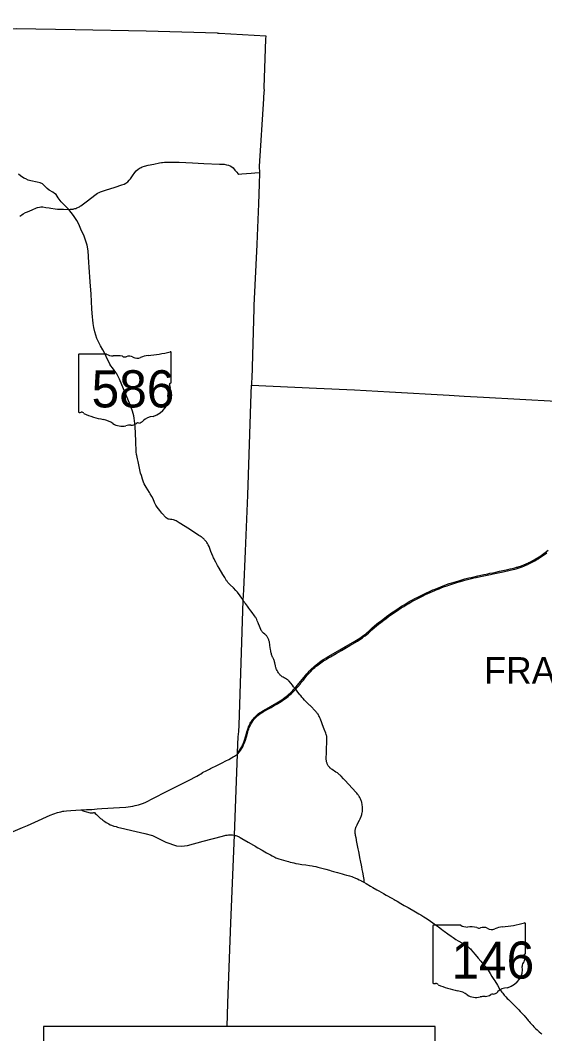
# Model space of a CAD drawing. Extents: x 1761803 to 2441803, y 509895 to 949895.
# Drawn here: x 2038611 to 2077957, y 835674 to 911653 of the extents above; entities that cross this region are included whole.
import ezdxf

# ---------------------------------------------------------------- set-up
doc = ezdxf.new("R2010")
doc.units = 0
for name, color, linetype in [('GM_X_County', 7, 'Continuous'), ('GM_X_County_Road', 7, 'Continuous'), ('GM_X_Minor_Lake', 7, 'Continuous'), ('GM_X_State_Location', 7, 'Continuous'), ('GM_X_Township_Road', 7, 'Continuous')]:
    doc.layers.add(name, color=color, linetype=linetype)

msp = doc.modelspace()

# ---------------------------------------------------------------- linework, layer by layer
at = {"layer": 'GM_X_County'}
for points in [[(2053400, 910687), (2048066, 910835), (2042725, 910935), (2038298, 911006), (2034985, 910966), (2034493, 910970), (2032253, 910990), (2029643, 910984), (2029631, 910665), (2029362, 910671), (2028709, 910661), (2023356, 910714), (2021728, 910742), (2020383, 910765), (2017999, 910806), (2014117, 910901), (2012614, 910938), (2008904, 911114), (2007002, 911215), (2006296, 911251), (2001880, 911522), (2001221, 911534), (2000194, 911593), (1998869, 911653)], [(2053400, 910687), (2053533, 910684), (2057032, 910483), (2057020, 910247), (2056883, 906617), (2056881, 906520), (2056896, 906456), (2056847, 905908), (2056862, 905765), (2056542, 900719), (2056569, 900221), (2056539, 899360), (2056483, 897899), (2056382, 895495), (2056352, 894837), (2056131, 890278), (2056126, 890080), (2056132, 890032), (2056081, 888304), (2055974, 884769), (2055968, 884562), (2055950, 884428), (2055947, 884303), (2060827, 884062), (2063674, 883938), (2066322, 883788), (2070793, 883546), (2071923, 883478), (2073355, 883403), (2078806, 883101)], [(2054132, 836223), (2054183, 837975), (2054401, 843988), (2054673, 850556), (2054916, 856641), (2054919, 856750), (2054960, 857935), (2055001, 858323), (2055024, 858817), (2055344, 868144), (2055389, 868960), (2055514, 871840), (2055675, 876040), (2055921, 883683), (2055947, 884303)]]:
    msp.add_lwpolyline(points, dxfattribs=at)
at = {"layer": 'GM_X_Minor_Lake'}
for points in [[(2043159, 897748), (2043164, 897752), (2043454, 897969), (2043549, 898040), (2044314, 898625), (2044412, 898680), (2044524, 898742), (2044623, 898784), (2045008, 898904), (2045734, 899132), (2046225, 899304), (2046407, 899368), (2046537, 899434), (2046617, 899484), (2046683, 899550), (2046787, 899663), (2046872, 899772), (2047037, 899982), (2047202, 900232), (2047300, 900357), (2047452, 900484), (2047618, 900593), (2047688, 900621), (2047759, 900655), (2047929, 900709), (2048217, 900781), (2048630, 900859), (2049051, 900960), (2049195, 900984), (2049290, 900996), (2049438, 901010), (2049872, 901014), (2050540, 901010), (2051529, 900968), (2052383, 900923), (2053556, 900872), (2053908, 900854), (2054094, 900823), (2054228, 900785), (2054346, 900741), (2054479, 900665), (2054579, 900585), (2054719, 900425), (2054857, 900253), (2054942, 900160), (2054996, 900120), (2055223, 900130), (2055592, 900161), (2055927, 900188), (2056211, 900220), (2056568, 900235)], [(2047305, 879302), (2047294, 879563), (2047287, 879832), (2047286, 880010), (2047267, 880785), (2047198, 881451), (2047128, 881989), (2047036, 882341), (2046852, 882829), (2046067, 884739), (2045962, 884941), (2045911, 885035), (2045852, 885135), (2045772, 885255), (2045534, 885586), (2045403, 885755), (2045335, 885870), (2045246, 886045), (2045088, 886370), (2045024, 886509), (2044809, 886947), (2044629, 887250), (2044344, 887785), (2044203, 888304), (2044137, 888614), (2044092, 888908), (2044057, 889188), (2044031, 889403), (2043985, 890011), (2043927, 891116), (2043856, 892033), (2043783, 893155), (2043764, 893487), (2043700, 894371), (2043637, 894784), (2043413, 895466), (2043167, 896000), (2042996, 896365), (2042862, 896635), (2042599, 897028), (2042258, 897474), (2042021, 897691), (2041816, 897905), (2041692, 898051), (2041456, 898345), (2041293, 898579), (2041189, 898673), (2041048, 898761), (2040783, 898909), (2040632, 899030), (2040354, 899308), (2040267, 899394), (2040116, 899455), (2039873, 899513), (2039404, 899623), (2039204, 899675), (2039026, 899758), (2038880, 899823), (2038621, 899990), (2038489, 900117)], [(2038580, 896972), (2038719, 897066), (2038840, 897145), (2038998, 897233), (2039156, 897299), (2039325, 897375), (2039499, 897451), (2039827, 897593), (2039903, 897613), (2040054, 897640), (2040149, 897657), (2040219, 897662), (2040300, 897660), (2040521, 897627), (2040770, 897580), (2040903, 897562), (2041226, 897512), (2041406, 897495), (2041590, 897486), (2041863, 897489), (2042258, 897474), (2042359, 897480), (2042419, 897485), (2042537, 897493), (2042583, 897500), (2042635, 897511), (2042707, 897530), (2042771, 897552), (2042866, 897586), (2042968, 897631), (2043053, 897675), (2043115, 897716), (2043159, 897748)], [(2055344, 868144), (2055242, 868319), (2055100, 868508), (2054914, 868768), (2054781, 868913), (2054606, 869097), (2054367, 869333), (2054307, 869390), (2054191, 869512), (2054125, 869598), (2054095, 869638), (2053957, 869865), (2053814, 870097), (2053531, 870579), (2053418, 870780), (2053279, 871019), (2053181, 871198), (2053146, 871266), (2053106, 871350), (2053072, 871417), (2053051, 871469), (2052980, 871647), (2052908, 871823), (2052880, 871898), (2052774, 872194), (2052713, 872327), (2052654, 872429), (2052612, 872495), (2052577, 872546), (2052528, 872610), (2052486, 872659), (2052443, 872707), (2052404, 872745), (2052352, 872794), (2052315, 872824), (2052278, 872855), (2052221, 872896), (2052179, 872924), (2052116, 872965), (2052059, 873002), (2052006, 873033), (2051689, 873252), (2051557, 873328), (2051306, 873492), (2050532, 873979), (2050307, 874115), (2050231, 874162), (2050176, 874182), (2050112, 874198), (2049975, 874215), (2049870, 874225), (2049782, 874242), (2049714, 874254), (2049633, 874297), (2049546, 874352), (2049235, 874709), (2049073, 874905), (2048869, 875160), (2048782, 875294), (2048680, 875511), (2048569, 875766), (2048475, 875947), (2048357, 876153), (2048298, 876260), (2048059, 876642), (2047977, 876778), (2047909, 876908), (2047854, 877029), (2047827, 877094), (2047776, 877253), (2047696, 877513), (2047640, 877694), (2047534, 878200), (2047453, 878584), (2047411, 878785), (2047344, 879012), (2047328, 879105), (2047305, 879302)], [(2054919, 856750), (2054990, 856828), (2055041, 856893), (2055089, 856959), (2055144, 857041), (2055187, 857111), (2055227, 857183), (2055264, 857256), (2055297, 857331), (2055334, 857423), (2055373, 857531), (2055424, 857687), (2055525, 858016), (2055613, 858302), (2055656, 858439), (2055702, 858579), (2055741, 858687), (2055772, 858763), (2055799, 858822), (2055828, 858881), (2055867, 858953), (2055908, 859024), (2055952, 859093), (2055998, 859160), (2056047, 859226), (2056097, 859290), (2056162, 859365), (2056229, 859436), (2056298, 859506), (2056357, 859562), (2056431, 859627), (2056495, 859678), (2056560, 859728), (2056614, 859765), (2056697, 859818), (2056809, 859885), (2057251, 860137), (2057334, 860184), (2057850, 860477), (2057977, 860552), (2058103, 860630), (2058226, 860712), (2058347, 860797), (2058466, 860884), (2058569, 860965), (2058658, 861038), (2058757, 861124), (2058855, 861212), (2058974, 861325), (2059055, 861406), (2059146, 861501), (2059213, 861573), (2059224, 861585), (2059300, 861671), (2059406, 861797), (2059770, 862241), (2060010, 862532), (2060105, 862644), (2060203, 862755), (2060292, 862851), (2060338, 862898), (2060395, 862957), (2060489, 863048), (2060597, 863149), (2060695, 863236), (2060808, 863330), (2060936, 863433), (2061053, 863522), (2061160, 863599), (2061268, 863672), (2061379, 863743), (2061561, 863853), (2061759, 863970), (2062581, 864448), (2063006, 864696), (2063574, 865025), (2063829, 865174), (2063955, 865251), (2064079, 865332), (2064187, 865406), (2064307, 865493), (2064424, 865583), (2064526, 865665), (2064639, 865760), (2064761, 865866), (2064787, 865890), (2065021, 866095), (2065195, 866245), (2065371, 866392), (2065562, 866548), (2065703, 866660), (2065924, 866830), (2066094, 866959), (2066253, 867075), (2066386, 867170), (2066588, 867310), (2066819, 867465), (2067025, 867600), (2067219, 867722), (2067401, 867833), (2067612, 867959), (2067797, 868066), (2068026, 868194), (2068213, 868296), (2068431, 868410), (2068635, 868515), (2068782, 868587), (2069078, 868727), (2069272, 868815), (2069572, 868946), (2069669, 868987), (2069784, 869036), (2069981, 869115), (2070210, 869205), (2070410, 869280), (2070579, 869342), (2070796, 869417), (2070983, 869479), (2071327, 869586), (2071500, 869639), (2071736, 869707), (2071958, 869767), (2072164, 869820), (2072260, 869844), (2072435, 869885), (2072541, 869909), (2072659, 869935), (2072947, 869998), (2073380, 870092), (2073556, 870130), (2073699, 870162), (2073828, 870190), (2074052, 870237), (2074293, 870288), (2074566, 870347), (2074950, 870431), (2075191, 870481), (2075351, 870515), (2075511, 870552), (2075607, 870576), (2075718, 870606), (2075844, 870641), (2075908, 870657), (2075971, 870675), (2076049, 870700), (2076127, 870726), (2076219, 870762), (2076437, 870846), (2076521, 870883), (2076603, 870919), (2076744, 870986), (2076775, 871000), (2076849, 871035), (2076936, 871080), (2077023, 871126), (2077166, 871206), (2077308, 871290), (2077419, 871359), (2077529, 871432), (2077677, 871535), (2077877, 871679), (2078210, 871918)], [(2064836, 865807), (2064895, 865858), (2064997, 865947), (2065194, 866121), (2065344, 866249), (2065495, 866374), (2065662, 866508), (2065881, 866680), (2066051, 866809), (2066209, 866927), (2066342, 867023), (2066529, 867155), (2066678, 867258), (2067005, 867476), (2067184, 867591), (2067379, 867713), (2067547, 867815), (2067759, 867940), (2067988, 868069), (2068189, 868180), (2068435, 868311), (2068624, 868409), (2068830, 868511), (2069007, 868596), (2069365, 868760), (2069530, 868833), (2069704, 868905), (2069817, 868953), (2070030, 869039), (2070229, 869117), (2070428, 869192), (2070629, 869265), (2070768, 869314), (2071127, 869431), (2071440, 869528), (2071645, 869589), (2071882, 869654), (2072056, 869700), (2072359, 869776), (2072566, 869825), (2072649, 869843), (2072807, 869877), (2073143, 869949), (2073640, 870058), (2073880, 870109), (2074089, 870154), (2074458, 870232), (2074826, 870312), (2075355, 870426), (2075579, 870478), (2075706, 870510), (2075801, 870537), (2075973, 870589), (2076114, 870634), (2076253, 870683), (2076391, 870735), (2076527, 870792), (2076692, 870864), (2076713, 870874), (2076811, 870919), (2076958, 870992), (2077074, 871054), (2077217, 871134), (2077358, 871217), (2077469, 871286), (2077593, 871367), (2077714, 871451), (2077928, 871603), (2078114, 871736)], [(2058057, 862632), (2058052, 862638), (2058011, 862690), (2057973, 862742), (2057939, 862796), (2057902, 862858), (2057874, 862912), (2057839, 862987), (2057820, 863032), (2057803, 863078), (2057784, 863140), (2057762, 863219), (2057748, 863283), (2057739, 863332), (2057732, 863364), (2057710, 863476), (2057691, 863555), (2057673, 863617), (2057657, 863663), (2057632, 863723), (2057604, 863782), (2057561, 863870), (2057540, 863914), (2057514, 863974), (2057495, 864020), (2057469, 864097), (2057450, 864160), (2057435, 864224), (2057421, 864288), (2057404, 864384), (2057388, 864475), (2057367, 864619), (2057344, 864777), (2057326, 864890), (2057311, 864987), (2057299, 865052), (2057284, 865115), (2057271, 865162), (2057255, 865208), (2057237, 865254), (2057210, 865313), (2057188, 865357), (2057164, 865399), (2057137, 865439), (2057108, 865478), (2057075, 865517), (2057042, 865552), (2057007, 865586), (2056957, 865628), (2056859, 865713), (2056810, 865757), (2056774, 865791), (2056752, 865815), (2056729, 865843), (2056707, 865875), (2056686, 865912), (2056653, 865981), (2056546, 866241), (2056488, 866394), (2056459, 866470), (2056393, 866638), (2056354, 866728), (2056334, 866772), (2056304, 866830), (2056280, 866872), (2056254, 866913), (2056188, 867006), (2056003, 867256), (2055905, 867387), (2055758, 867585), (2055661, 867717), (2055582, 867821), (2055505, 867927), (2055466, 867980), (2055437, 868019), (2055418, 868045), (2055389, 868084), (2055344, 868144)], [(2059255, 861484), (2059270, 861500), (2059272, 861503), (2059338, 861576), (2059434, 861688), (2059622, 861915), (2059695, 862004), (2059853, 862192), (2060041, 862420), (2060145, 862547), (2060230, 862647), (2060307, 862733), (2060397, 862828), (2060514, 862943), (2060621, 863045), (2060706, 863122), (2060818, 863218), (2060933, 863312), (2061050, 863402), (2061169, 863490), (2061263, 863556), (2061372, 863629), (2061511, 863716), (2061651, 863801), (2061893, 863941), (2062317, 864189), (2062701, 864411), (2063339, 864782), (2063735, 865014), (2063905, 865114), (2064058, 865208), (2064168, 865280), (2064275, 865355), (2064394, 865442), (2064485, 865512), (2064600, 865604), (2064726, 865710), (2064836, 865807)], [(2059309, 861452), (2059290, 861475), (2059270, 861500), (2059229, 861553), (2059213, 861573), (2059116, 861693), (2059022, 861806), (2058898, 861957), (2058781, 862095), (2058738, 862140), (2058704, 862172), (2058672, 862199), (2058627, 862232), (2058574, 862267), (2058508, 862303), (2058397, 862362), (2058324, 862403), (2058270, 862436), (2058230, 862464), (2058191, 862494), (2058156, 862526), (2058117, 862563), (2058086, 862599), (2058057, 862632)], [(2055653, 858197), (2055665, 858234), (2055685, 858299), (2055718, 858406), (2055760, 858530), (2055795, 858623), (2055832, 858714), (2055873, 858803), (2055918, 858891), (2055958, 858963), (2056001, 859033), (2056047, 859101), (2056095, 859168), (2056145, 859233), (2056198, 859296), (2056253, 859357), (2056310, 859416), (2056370, 859472), (2056432, 859526), (2056496, 859578), (2056562, 859627), (2056630, 859673), (2056713, 859726), (2056840, 859802), (2057195, 860007), (2057436, 860143), (2057666, 860274), (2057908, 860412), (2058063, 860504), (2058188, 860582), (2058284, 860645), (2058391, 860721), (2058510, 860808), (2058613, 860889), (2058701, 860962), (2058825, 861070), (2058959, 861191), (2059066, 861292), (2059182, 861408), (2059255, 861484)], [(2060207, 860414), (2060164, 860456), (2060141, 860479), (2060061, 860561), (2059937, 860691), (2059827, 860813), (2059743, 860909), (2059651, 861021), (2059628, 861049), (2059595, 861090), (2059533, 861167), (2059442, 861283), (2059330, 861424), (2059309, 861452)], [(2064383, 847034), (2064408, 847086), (2064417, 847113), (2064418, 847130), (2064418, 847163), (2064416, 847195), (2064409, 847243), (2064388, 847356), (2064302, 847789), (2064265, 847982), (2064224, 848190), (2064199, 848319), (2064156, 848544), (2064089, 848898), (2064057, 849058), (2063999, 849347), (2063961, 849539), (2063840, 850150), (2063824, 850239), (2063798, 850368), (2063767, 850529), (2063753, 850610), (2063743, 850675), (2063742, 850690), (2063738, 850740), (2063735, 850804), (2063735, 850844), (2063737, 850877), (2063739, 850910), (2063745, 850951), (2063755, 851004), (2063766, 851052), (2063779, 851100), (2063796, 851149), (2063814, 851196), (2063829, 851231), (2063877, 851336), (2063918, 851415), (2064058, 851694), (2064101, 851782), (2064155, 851901), (2064180, 851962), (2064207, 852039), (2064231, 852117), (2064247, 852181), (2064260, 852245), (2064273, 852326), (2064284, 852423), (2064287, 852490), (2064288, 852554), (2064287, 852619), (2064280, 852717), (2064268, 852815), (2064255, 852896), (2064240, 852976), (2064225, 853040), (2064211, 853087), (2064188, 853148), (2064187, 853151), (2064163, 853208), (2064128, 853282), (2064075, 853384), (2064035, 853456), (2064000, 853512), (2063991, 853525), (2063954, 853579), (2063915, 853632), (2063853, 853708), (2063789, 853783), (2062978, 854664), (2062865, 854784), (2062686, 854976), (2062606, 855058), (2062570, 855091), (2062520, 855134), (2062469, 855175), (2062403, 855222), (2062293, 855295), (2062015, 855473), (2061960, 855511), (2061908, 855552), (2061871, 855586), (2061840, 855617), (2061825, 855633), (2061806, 855653), (2061773, 855689), (2061743, 855728), (2061715, 855770), (2061689, 855814), (2061666, 855860), (2061646, 855905), (2061628, 855951), (2061613, 855998), (2061595, 856061), (2061584, 856110), (2061580, 856134), (2061576, 856159), (2061570, 856208), (2061568, 856257), (2061571, 856460), (2061578, 856618), (2061589, 856897), (2061597, 857080), (2061613, 857481), (2061622, 857773), (2061622, 857825), (2061619, 857876), (2061616, 857910), (2061612, 857941), (2061604, 857988), (2061591, 858036), (2061572, 858099), (2061533, 858207), (2061417, 858510), (2061368, 858631), (2061123, 859256), (2061086, 859347), (2061054, 859422), (2061019, 859496), (2060981, 859568), (2060948, 859624), (2060918, 859665), (2060880, 859717), (2060842, 859764), (2060815, 859795), (2060784, 859829), (2060349, 860271), (2060303, 860317), (2060211, 860410), (2060207, 860414)], [(2055448, 857543), (2055449, 857545), (2055496, 857685), (2055573, 857936), (2055653, 858197)], [(2054916, 856641), (2055063, 856810), (2055112, 856875), (2055158, 856943), (2055211, 857025), (2055252, 857096), (2055298, 857183), (2055334, 857256), (2055368, 857331), (2055404, 857422), (2055448, 857543)], [(2053219, 855719), (2053460, 855840), (2053770, 855991), (2054037, 856127), (2054259, 856243), (2054466, 856364), (2054578, 856428), (2054690, 856493), (2054829, 856582), (2054916, 856641)], [(2052799, 855509), (2052873, 855548), (2053091, 855655), (2053219, 855719)], [(2044377, 852523), (2044736, 852548), (2046045, 852630), (2046539, 852666), (2047061, 852732), (2047241, 852772), (2047493, 852839), (2047846, 852964), (2048026, 853045), (2048606, 853336), (2049574, 853829), (2050172, 854133), (2050487, 854291), (2051371, 854745), (2051699, 854908)], [(2051699, 854908), (2051867, 854992), (2052289, 855244)], [(2052289, 855244), (2052291, 855246), (2052613, 855413)], [(2052613, 855413), (2052799, 855509)], [(2043202, 852465), (2043571, 852487), (2043732, 852490)], [(2043732, 852490), (2043968, 852494), (2044377, 852523)], [(2037403, 850466), (2037527, 850555), (2037760, 850689), (2038073, 850829), (2038433, 850980), (2038782, 851135), (2039157, 851294), (2039706, 851526), (2040851, 852049), (2041140, 852168), (2041400, 852254), (2041527, 852289), (2041662, 852320), (2041799, 852350), (2041881, 852360), (2042072, 852392), (2042412, 852415), (2043160, 852462), (2043202, 852465)], [(2043202, 852465), (2043256, 852414), (2043324, 852374), (2043406, 852351), (2043581, 852315), (2043867, 852243), (2043983, 852229), (2044029, 852231), (2044080, 852239), (2044122, 852248)], [(2044122, 852248), (2044172, 852259), (2044232, 852192), (2044319, 852100), (2044452, 851975), (2044633, 851815), (2044718, 851750), (2044800, 851687), (2044946, 851585), (2045066, 851508), (2045150, 851459), (2045250, 851403), (2045368, 851345), (2045444, 851310), (2045635, 851247), (2045804, 851198), (2045912, 851156), (2046467, 851030), (2046979, 850909), (2047951, 850694), (2048527, 850526), (2049524, 850045), (2050325, 849754), (2050711, 849724), (2051155, 849790), (2052326, 850118), (2053781, 850491), (2054036, 850549), (2054128, 850571), (2054242, 850585), (2054308, 850587), (2054406, 850592), (2054523, 850580), (2054673, 850556)], [(2054673, 850556), (2054722, 850544), (2054792, 850525), (2054851, 850505), (2054915, 850482), (2054972, 850457), (2055032, 850430), (2055104, 850391), (2055231, 850319), (2055717, 850041), (2056097, 849817), (2056211, 849751), (2056239, 849735), (2056438, 849621), (2056750, 849439), (2056949, 849323), (2057076, 849248), (2057375, 849077), (2057519, 848999), (2057607, 848954), (2057711, 848906), (2057786, 848873), (2057863, 848844), (2058002, 848796), (2058194, 848736), (2058543, 848633), (2058741, 848576), (2058855, 848544), (2059005, 848505), (2059136, 848475), (2059276, 848447), (2059476, 848412), (2059737, 848373), (2060044, 848331), (2060320, 848289), (2060499, 848261), (2060612, 848241), (2060772, 848205), (2060868, 848182), (2060932, 848167), (2061138, 848111), (2061343, 848055), (2061533, 848002), (2061802, 847927), (2061927, 847892), (2062102, 847844), (2062418, 847755), (2062766, 847659), (2062909, 847619), (2063082, 847570), (2063209, 847534), (2063319, 847501), (2063474, 847449), (2063582, 847410), (2063705, 847361), (2063886, 847286), (2063900, 847280), (2064036, 847218), (2064154, 847160), (2064190, 847141), (2064241, 847114), (2064383, 847034)], [(2064383, 847034), (2064549, 846943), (2064888, 846746), (2065072, 846637), (2065355, 846472), (2065511, 846381), (2065852, 846184), (2066066, 846062), (2066479, 845826), (2066653, 845728), (2066736, 845681), (2066879, 845600), (2067150, 845446), (2067406, 845299), (2067706, 845128), (2068262, 844811), (2068517, 844663), (2068658, 844578), (2068895, 844430), (2069129, 844279), (2069389, 844107), (2069552, 843995), (2069766, 843844), (2069993, 843680), (2070212, 843519), (2070345, 843422), (2070416, 843370), (2070694, 843166), (2070946, 842982), (2071080, 842888), (2071188, 842814), (2071299, 842743), (2071467, 842641), (2071778, 842458), (2071831, 842425)], [(2071831, 842425), (2072031, 842304), (2072116, 842252), (2072169, 842215), (2072219, 842177), (2072246, 842154), (2072269, 842135), (2072318, 842090), (2072378, 842027), (2072431, 841966), (2072569, 841803), (2072741, 841603), (2072975, 841329), (2073156, 841119), (2073262, 840997), (2073370, 840873), (2073478, 840748), (2073552, 840662), (2073604, 840594), (2073651, 840527), (2073714, 840430), (2073863, 840192), (2074000, 839968), (2074138, 839746), (2074208, 839634), (2074276, 839524), (2074327, 839440), (2074412, 839303), (2074574, 839041), (2074627, 838960), (2074673, 838891), (2074740, 838797), (2074809, 838704), (2074859, 838639), (2074910, 838575), (2074965, 838512), (2075043, 838429), (2075150, 838326), (2075230, 838248), (2075442, 838042), (2075547, 837938), (2075745, 837742), (2075882, 837601), (2076004, 837469), (2076115, 837348), (2076215, 837239), (2076293, 837154), (2076401, 837031), (2076488, 836933), (2076491, 836930), (2076660, 836735), (2076724, 836661), (2076788, 836586), (2076864, 836500), (2076974, 836379), (2077063, 836280), (2077141, 836197), (2077219, 836115), (2077299, 836037), (2077387, 835955), (2077528, 835826), (2077665, 835704), (2077739, 835640)]]:
    msp.add_lwpolyline(points, dxfattribs=at)
at = {"layer": 'GM_X_State_Location'}
msp.add_lwpolyline([(2040349, 821388), (2069725, 821388), (2069725, 836223), (2040349, 836223)], close=True, dxfattribs=at)
at = {"layer": 'GM_X_Township_Road'}
for p, q in [((2049936, 884524), (2049936, 886735)), ((2042975, 886557), (2042975, 882331)), ((2045082, 886630), (2043043, 886630)), ((2049935, 884524), (2049936, 884524)), ((2069555, 843731), (2069555, 839505)), ((2071662, 843804), (2069623, 843804)), ((2076516, 841698), (2076516, 843909)), ((2076515, 841698), (2076516, 841698))]:
    msp.add_line(p, q, dxfattribs=at)
for centre, major_axis, start_param, end_param in [((2047456, 892392), (7382, 0), 4.814394, 5.042369), ((2049859, 886744), (77.5, 0), 6.141152, 7.989035), ((2043055, 886566), (80.6, 0), 1.712693, 3.28349), ((2045567, 887120), (782, 0), 4.042523, 4.731795), ((2045827, 884257), (2808, 0), 1.404758, 1.657858), ((2046464, 886588), (226, 0), 3.836095, 5.185415), ((2046796, 886099), (469, 0), 0.950623, 2.079405), ((2047401, 886769), (564, 0), 4.081561, 5.145723), ((2048398, 885339), (1485, 0), 1.699011, 2.107814), ((2049918, 884361), (120, 0), 1.883978, 3.671073), ((2049853, 884515), (82.9, 0), 5.05454, 6.418171), ((2050213, 883598), (524, 0), 2.387724, 3.262537), ((2049155, 884082), (720, 0), 5.934695, 6.695948), ((2047870, 883317), (1846, 0), 5.101752, 6.440018), ((2043055, 882321), (81.4, 0), 3.00124, 4.508301), ((2043068, 882754), (621, 0), 4.665946, 4.897461), ((2043195, 882087), (224, 0), 0.519207, 1.627899), ((2046021, 885884), (5331, 0), 4.195997, 4.488961), ((2044432, 880432), (1668, 0), 0.823519, 1.323587), ((2046236, 882066), (1058, 0), 4.026481, 4.996735), ((2046925, 881749), (564, 0), 4.691044, 5.507374), ((2047435, 881340), (159, 0), 1.147584, 2.315152), ((2047367, 881921), (597, 0), 4.937069, 5.64225), ((2048648, 881144), (1011, 0), 1.647645, 2.488434), ((2046847, 880604), (870, 0), 1.495662, 1.94098), ((2069635, 843740), (80.6, 0), 1.712693, 3.28349), ((2072147, 844295), (782, 0), 4.042523, 4.731795), ((2072407, 841431), (2808, 0), 1.404758, 1.657858), ((2073044, 843762), (226, 0), 3.836095, 5.185415), ((2073375, 843274), (469, 0), 0.950623, 2.079405), ((2073981, 843944), (564, 0), 4.081561, 5.145723), ((2074978, 842513), (1485, 0), 1.699011, 2.107814), ((2074036, 849566), (7382, 0), 4.814394, 5.042369), ((2076439, 843918), (77.5, 0), 6.141152, 7.989035), ((2076498, 841535), (120, 0), 1.883978, 3.671073), ((2075735, 841256), (720, 0), 5.934695, 6.695948), ((2076433, 841689), (82.9, 0), 5.05454, 6.418171), ((2074450, 840491), (1846, 0), 5.101752, 6.440018), ((2076793, 840772), (524, 0), 2.387724, 3.262537), ((2069635, 839495), (81.4, 0), 3.00124, 4.508301), ((2069648, 839928), (621, 0), 4.665946, 4.897461), ((2069775, 839261), (224, 0), 0.519207, 1.627899), ((2072601, 843058), (5331, 0), 4.195997, 4.488961), ((2071012, 837606), (1668, 0), 0.823519, 1.323587), ((2073947, 839095), (597, 0), 4.937069, 5.64225), ((2075228, 838318), (1011, 0), 1.647645, 2.488434), ((2072816, 839240), (1058, 0), 4.026481, 4.996735), ((2073427, 837779), (870, 0), 1.495662, 1.94098), ((2073505, 838923), (564, 0), 4.691044, 5.507374), ((2074015, 838514), (159, 0), 1.147584, 2.315152)]:
    msp.add_ellipse(centre, major_axis=major_axis, ratio=0.8, start_param=start_param, end_param=end_param, dxfattribs=at)

# ---------------------------------------------------------------- texts
at = {"layer": 'GM_X_County_Road'}
msp.add_text('FRAZEYSBURG', height=2000, rotation=0.00001, dxfattribs=at).set_placement((2073413, 861908))
at = {"layer": 'GM_X_Township_Road'}
for s, p in [('586', (2043962, 882629)), ('146', (2070955, 839803))]:
    msp.add_text(s, height=2784.4, dxfattribs=at).set_placement(p)

doc.saveas('drawing.dxf')
